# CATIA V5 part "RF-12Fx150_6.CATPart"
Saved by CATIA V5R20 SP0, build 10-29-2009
Part number: _RF-12Fx150
Definition: NONE
Nomenclature: _RF-12Fx150
Source: Unknown
Description: PART-_RF-12Fx150-DESC
Bounding box of the stored display mesh (mm): x -150 to 24, y -6.65 to 6.65, z -6.65 to 6.65
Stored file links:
  C:\Users\Utente\Desktop\IO LAVORO\3D X SITO CF\X SITO\PLASTICA\RFF\RF-12Fx150_6.CATPart

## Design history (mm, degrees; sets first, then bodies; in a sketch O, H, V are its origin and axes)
Body1 "_RF-12Fx150" (main body)
  Solid1: solid without history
